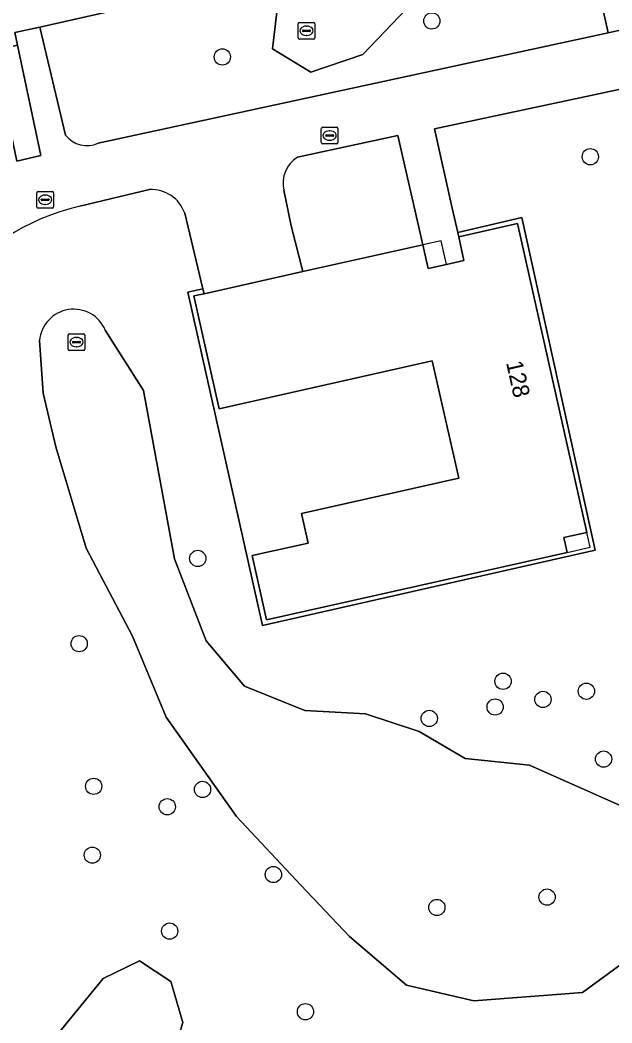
# Model space of a CAD drawing. Extents: x 156661 to 157576, y 383570 to 384425.
# Drawn here: x 156758.2 to 156793.8, y 383881.2 to 383941.5 of the extents above; entities that cross this region are included whole.
import ezdxf

# ---------------------------------------------------------------- set-up
doc = ezdxf.new("R2010")
doc.units = 0
for name, color, linetype in [('IMGEO_Boom', 7, 'Continuous'), ('IMGEO_Erf', 7, 'Continuous'), ('IMGEO_Groenvoorziening', 7, 'Continuous'), ('IMGEO_Meer_plas_ven_vijver', 7, 'Continuous'), ('IMGEO_Pand', 7, 'Continuous'), ('IMGEO_Pand_nummerreeks', 7, 'Continuous'), ('IMGEO_Pand_overbouw', 7, 'Continuous'), ('IMGEO_Rijbaan_lokaal_gesloten', 7, 'Continuous'), ('IMGEO_Rioolput', 7, 'Continuous'), ('IMGEO_Voetpad_open', 7, 'Continuous')]:
    doc.layers.add(name, color=color, linetype=linetype)

msp = doc.modelspace()

# ---------------------------------------------------------------- linework, layer by layer
at = {"layer": 'IMGEO_Boom'}
for centre in [(156782.999, 383941.466), (156770.4, 383939.3), (156792.529, 383933.304), (156768.925, 383909.156), (156761.792, 383904.036), (156787.283, 383901.774), (156792.293, 383901.175), (156786.807, 383900.229), (156789.68, 383900.681), (156782.842, 383899.539), (156793.327, 383897.097), (156762.662, 383895.46), (156769.21, 383895.271), (156767.091, 383894.232), (156762.584, 383891.322), (156773.472, 383890.158), (156789.932, 383888.802), (156783.301, 383888.177), (156767.234, 383886.756), (156775.401, 383881.913)]:
    msp.add_circle(centre, 0.489, dxfattribs=at)
at = {"layer": 'IMGEO_Erf'}
msp.add_lwpolyline([(156783.017, 383921.041), (156770.213, 383918.148), (156768.69, 383924.935), (156769.3, 383925.071), (156769.229, 383925.367), (156768.321, 383925.155), (156772.807, 383905.13), (156792.818, 383909.646), (156788.41, 383929.644), (156784.555, 383928.753), (156784.613, 383928.493), (156788.143, 383929.281), (156792.312, 383910.722), (156790.931, 383910.412), (156791.131, 383909.52), (156773.05, 383905.464), (156772.187, 383909.327), (156775.564, 383910.081), (156775.168, 383911.852), (156784.613, 383913.976)], close=True, dxfattribs=at)
at = {"layer": 'IMGEO_Groenvoorziening'}
for points in [[(156762.934, 383934.118), (156793.6, 383940.758), (156778.599, 384008.292)], [(156751.719, 383933.758), (156750.78, 383938.387), (156745.551, 383937.219), (156741.236, 383956.679), (156746.086, 383957.762), (156760.64, 383960.974), (156761.956, 383955.261), (156762.554, 383952.572), (156762.026, 383952.455), (156764.312, 383942.195), (156759.416, 383941.099), (156760.97, 383934.592)], [(156783.667, 383944.503), (156778.843, 383939.451), (156775.723, 383938.382), (156773.42, 383939.788), (156774.037, 383945.068)], [(156801.01, 383907.365), (156795.487, 383906.115), (156795.088, 383907.896), (156800.623, 383909.14), (156794.353, 383937.37), (156783.169, 383934.99), (156784.232, 383930.211), (156784.555, 383928.753), (156788.41, 383929.644), (156792.818, 383909.646), (156772.807, 383905.13), (156768.321, 383925.155), (156769.229, 383925.367), (156768.136, 383929.92)], [(156775.245, 383926.4), (156782.461, 383928.012), (156780.961, 383934.576), (156774.922, 383933.277)], [(156766.03, 383931.333), (156761.825, 383930.332)], [(156774.107, 383931.292), (156774.533, 383929.146), (156775.245, 383926.4)], [(156763.361, 383922.88), (156765.651, 383919.251), (156767.525, 383909.129), (156769.434, 383904.195), (156771.726, 383901.474), (156775.366, 383900.016), (156779.003, 383899.812), (156782.244, 383898.751), (156785.006, 383897.128), (156788.874, 383896.741), (156795.235, 383893.904), (156797.126, 383892.013), (156797.298, 383887.371), (156795.493, 383885.566), (156792.055, 383883.073), (156785.522, 383882.557), (156781.482, 383883.503), (156778.043, 383886.426), (156775.121, 383889.52), (156771.252, 383893.646), (156767.023, 383899.625), (156764.997, 383904.478)], [(156764.997, 383904.478), (156762.212, 383909.779), (156760.391, 383915.857), (156759.636, 383919.089), (156759.409, 383922.264)]]:
    msp.add_lwpolyline(points, dxfattribs=at)
for points in [[(156758.081, 383940.019), (156756.644, 383939.698), (156758.042, 383933.044), (156759.476, 383933.381)], [(156767.299, 383883.721), (156768.021, 383881.267), (156767.313, 383878.874), (156764.354, 383873.446), (156760.744, 383872.951), (156759.648, 383875.982), (156758.573, 383877.099), (156759.562, 383879.076), (156760.194, 383880.185), (156763.24, 383883.907), (156765.415, 383884.973)], [(156767.313, 383878.874), (156768.021, 383881.267), (156767.299, 383883.721), (156765.415, 383884.973), (156763.24, 383883.907), (156760.194, 383880.185), (156759.562, 383879.076), (156758.573, 383877.099), (156759.648, 383875.982), (156760.744, 383872.951), (156764.354, 383873.446)]]:
    msp.add_lwpolyline(points, close=True, dxfattribs=at)
for centre, radius, start, end in [((156762.262, 383935.638), 1.662, 219.00126, 293.86167), ((156775.898, 383931.716), 1.841, 122.03016, 193.32576), ((156766.126, 383929.2), 2.135, 19.70299, 92.57851), ((156765.181, 383916.263), 14.464, 103.41782, 179.48447), ((156761.462, 383922.078), 2.061, 22.89543, 174.82343)]:
    msp.add_arc(centre, radius, start, end, dxfattribs=at)
at = {"layer": 'IMGEO_Meer_plas_ven_vijver'}
for points in [[(156774.037, 383945.068), (156773.42, 383939.788), (156775.723, 383938.382), (156778.843, 383939.451), (156783.667, 383944.503)], [(156782.244, 383898.751), (156779.003, 383899.812), (156775.366, 383900.016), (156771.726, 383901.474), (156769.434, 383904.195), (156767.525, 383909.129), (156765.651, 383919.251), (156763.361, 383922.88)], [(156759.409, 383922.264), (156759.636, 383919.089), (156760.391, 383915.857), (156762.212, 383909.779), (156764.997, 383904.478), (156767.023, 383899.625), (156771.252, 383893.646), (156775.121, 383889.52), (156778.043, 383886.426), (156781.482, 383883.503), (156785.522, 383882.557), (156792.055, 383883.073), (156795.493, 383885.566), (156797.298, 383887.371), (156797.126, 383892.013), (156795.235, 383893.904), (156788.874, 383896.741), (156785.006, 383897.128), (156782.244, 383898.751)]]:
    msp.add_lwpolyline(points, dxfattribs=at)
msp.add_arc((156761.462, 383922.078), 2.061, 22.89543, 174.82343, dxfattribs=at)
at = {"layer": 'IMGEO_Pand'}
for points in [[(156762.026, 383952.455), (156762.554, 383952.572), (156761.956, 383955.261), (156756.462, 383954.041), (156757.728, 383948.318), (156748.639, 383946.279), (156746.086, 383957.762), (156741.236, 383956.679), (156745.551, 383937.219), (156750.78, 383938.387), (156756.644, 383939.698), (156758.081, 383940.019), (156757.925, 383940.765), (156759.416, 383941.099), (156764.312, 383942.195)], [(156788.143, 383929.281), (156784.613, 383928.493), (156784.932, 383927.058), (156783.882, 383926.824), (156782.78, 383926.578), (156782.461, 383928.012), (156775.245, 383926.4), (156769.3, 383925.071), (156768.69, 383924.935), (156770.213, 383918.148), (156783.017, 383921.041), (156784.613, 383913.976), (156775.168, 383911.852), (156775.564, 383910.081), (156772.187, 383909.327), (156773.05, 383905.464), (156791.131, 383909.52), (156790.931, 383910.412), (156792.312, 383910.722)]]:
    msp.add_lwpolyline(points, close=True, dxfattribs=at)
at = {"layer": 'IMGEO_Pand_overbouw'}
for points in [[(156783.563, 383928.258), (156782.461, 383928.012), (156782.78, 383926.578), (156783.882, 383926.824)], [(156792.312, 383910.722), (156790.931, 383910.412), (156791.131, 383909.52), (156792.512, 383909.829)]]:
    msp.add_lwpolyline(points, close=True, dxfattribs=at)
at = {"layer": 'IMGEO_Rijbaan_lokaal_gesloten'}
for points in [[(156797.583, 383941.621), (156795.59, 383941.189), (156793.6, 383940.758), (156762.934, 383934.118)], [(156760.97, 383934.592), (156759.416, 383941.099), (156757.925, 383940.765), (156758.081, 383940.019), (156759.476, 383933.381), (156758.042, 383933.044), (156756.644, 383939.698), (156750.78, 383938.387), (156751.719, 383933.758)], [(156774.922, 383933.277), (156780.961, 383934.576), (156782.461, 383928.012), (156782.78, 383926.578), (156783.882, 383926.824), (156784.932, 383927.058), (156784.613, 383928.493), (156784.555, 383928.753), (156784.232, 383930.211), (156783.169, 383934.99), (156794.353, 383937.37), (156797.015, 383937.936)], [(156761.825, 383930.332), (156766.03, 383931.333)], [(156768.136, 383929.92), (156769.229, 383925.367), (156769.3, 383925.071), (156775.245, 383926.4), (156774.533, 383929.146), (156774.107, 383931.292)]]:
    msp.add_lwpolyline(points, dxfattribs=at)
for centre, radius, start, end in [((156762.262, 383935.638), 1.662, 219.00126, 293.86167), ((156775.898, 383931.716), 1.841, 122.03016, 193.32576), ((156766.126, 383929.2), 2.135, 19.70299, 92.57851), ((156765.181, 383916.263), 14.464, 103.41782, 179.48447)]:
    msp.add_arc(centre, radius, start, end, dxfattribs=at)
at = {"layer": 'IMGEO_Rioolput'}
for p, q in [((156774.963, 383940.447), (156774.963, 383941.299)), ((156775.038, 383941.373), (156775.89, 383941.373)), ((156775.451, 383941.153), (156775.476, 383941.153)), ((156775.964, 383941.299), (156775.964, 383940.447)), ((156775.222, 383940.867), (156775.222, 383940.879)), ((156775.66, 383940.83), (156775.262, 383940.83)), ((156775.265, 383940.916), (156775.663, 383940.916)), ((156775.474, 383940.593), (156775.449, 383940.593)), ((156775.706, 383940.879), (156775.706, 383940.867)), ((156775.89, 383940.373), (156775.038, 383940.373)), ((156776.354, 383934.15), (156776.354, 383935.002)), ((156776.429, 383935.076), (156777.281, 383935.076)), ((156777.355, 383935.002), (156777.355, 383934.15)), ((156776.613, 383934.57), (156776.613, 383934.582)), ((156777.051, 383934.533), (156776.653, 383934.533)), ((156776.656, 383934.619), (156777.054, 383934.619)), ((156776.842, 383934.856), (156776.867, 383934.856)), ((156777.097, 383934.582), (156777.097, 383934.57)), ((156777.281, 383934.076), (156776.429, 383934.076)), ((156776.865, 383934.296), (156776.84, 383934.296)), ((156759.247, 383930.291), (156759.247, 383931.143)), ((156759.322, 383931.217), (156760.174, 383931.217)), ((156759.549, 383930.76), (156759.947, 383930.76)), ((156759.735, 383930.997), (156759.76, 383930.997)), ((156760.248, 383931.143), (156760.248, 383930.291)), ((156760.174, 383930.217), (156759.322, 383930.217)), ((156759.506, 383930.711), (156759.506, 383930.723)), ((156759.944, 383930.674), (156759.546, 383930.674)), ((156759.758, 383930.437), (156759.733, 383930.437)), ((156759.99, 383930.723), (156759.99, 383930.711)), ((156761.132, 383921.734), (156761.132, 383922.586)), ((156761.207, 383922.66), (156762.059, 383922.66)), ((156761.62, 383922.44), (156761.645, 383922.44)), ((156762.133, 383922.586), (156762.133, 383921.734)), ((156761.391, 383922.154), (156761.391, 383922.166)), ((156761.829, 383922.117), (156761.431, 383922.117)), ((156761.434, 383922.203), (156761.832, 383922.203)), ((156761.643, 383921.88), (156761.618, 383921.88)), ((156761.875, 383922.166), (156761.875, 383922.154)), ((156762.059, 383921.66), (156761.207, 383921.66))]:
    msp.add_line(p, q, dxfattribs=at)
for points in [[(156774.963, 383940.447), (156774.963, 383941.299)], [(156775.038, 383941.373), (156775.89, 383941.373)], [(156775.964, 383941.299), (156775.964, 383940.447)], [(156775.89, 383940.373), (156775.038, 383940.373)], [(156776.354, 383934.15), (156776.354, 383935.002)], [(156776.429, 383935.076), (156777.281, 383935.076)], [(156777.355, 383935.002), (156777.355, 383934.15)], [(156777.281, 383934.076), (156776.429, 383934.076)], [(156759.247, 383930.291), (156759.247, 383931.143)], [(156759.322, 383931.217), (156760.174, 383931.217)], [(156760.248, 383931.143), (156760.248, 383930.291)], [(156760.174, 383930.217), (156759.322, 383930.217)], [(156761.132, 383921.734), (156761.132, 383922.586)], [(156761.207, 383922.66), (156762.059, 383922.66)], [(156762.133, 383922.586), (156762.133, 383921.734)], [(156762.059, 383921.66), (156761.207, 383921.66)]]:
    msp.add_lwpolyline(points, dxfattribs=at)
for centre, radius, start, end in [((156775.04, 383941.297), 0.0765, 91.55205, 178.44795), ((156775.04, 383941.297), 0.0765, 91.55205, 178.44795), ((156775.888, 383941.297), 0.0765, 1.55205, 88.44795), ((156775.888, 383941.297), 0.0765, 1.55205, 88.44795), ((156775.04, 383940.449), 0.0765, 181.55205, 268.44795), ((156775.04, 383940.449), 0.0765, 181.55205, 268.44795), ((156775.262, 383940.876), 0.0403, 85.87752, 175.75265), ((156775.259, 383940.866), 0.0366, 178.93798, 274.71019), ((156775.663, 383940.873), 0.043, 264.86636, 352.45326), ((156775.667, 383940.878), 0.0386, 1.73085, 96.63898), ((156775.888, 383940.449), 0.0765, 271.55205, 358.44795), ((156775.888, 383940.449), 0.0765, 271.55205, 358.44795), ((156776.431, 383935), 0.0765, 91.55205, 178.44795), ((156776.431, 383935), 0.0765, 91.55205, 178.44795), ((156777.279, 383935), 0.0765, 1.55205, 88.44795), ((156777.279, 383935), 0.0765, 1.55205, 88.44795), ((156776.653, 383934.579), 0.0403, 85.87752, 175.75265), ((156776.65, 383934.569), 0.0366, 178.93798, 274.71019), ((156777.054, 383934.576), 0.043, 264.86636, 352.45326), ((156777.058, 383934.581), 0.0386, 1.73085, 96.63898), ((156776.431, 383934.152), 0.0765, 181.55205, 268.44795), ((156776.431, 383934.152), 0.0765, 181.55205, 268.44795), ((156777.279, 383934.152), 0.0765, 271.55205, 358.44795), ((156777.279, 383934.152), 0.0765, 271.55205, 358.44795), ((156759.324, 383931.141), 0.0765, 91.55205, 178.44795), ((156759.324, 383931.141), 0.0765, 91.55205, 178.44795), ((156759.546, 383930.72), 0.0403, 85.87752, 175.75265), ((156759.951, 383930.722), 0.0386, 1.73085, 96.63898), ((156760.172, 383931.141), 0.0765, 1.55205, 88.44795), ((156760.172, 383931.141), 0.0765, 1.55205, 88.44795), ((156759.324, 383930.293), 0.0765, 181.55205, 268.44795), ((156759.324, 383930.293), 0.0765, 181.55205, 268.44795), ((156759.543, 383930.71), 0.0366, 178.93798, 274.71019), ((156759.947, 383930.717), 0.043, 264.86636, 352.45326), ((156760.172, 383930.293), 0.0765, 271.55205, 358.44795), ((156760.172, 383930.293), 0.0765, 271.55205, 358.44795), ((156761.209, 383922.584), 0.0765, 91.55205, 178.44795), ((156761.209, 383922.584), 0.0765, 91.55205, 178.44795), ((156762.057, 383922.584), 0.0765, 1.55205, 88.44795), ((156762.057, 383922.584), 0.0765, 1.55205, 88.44795), ((156761.209, 383921.736), 0.0765, 181.55205, 268.44795), ((156761.209, 383921.736), 0.0765, 181.55205, 268.44795), ((156761.431, 383922.163), 0.0403, 85.87752, 175.75265), ((156761.428, 383922.153), 0.0366, 178.93798, 274.71019), ((156761.832, 383922.16), 0.043, 264.86636, 352.45326), ((156761.836, 383922.165), 0.0386, 1.73085, 96.63898), ((156762.057, 383921.736), 0.0765, 271.55205, 358.44795), ((156762.057, 383921.736), 0.0765, 271.55205, 358.44795)]:
    msp.add_arc(centre, radius, start, end, dxfattribs=at)
for centre, major_axis, ratio, start_param, end_param in [((156775.45, 383940.873), (-0.387, 0.002), 0.722429, 4.712389, 7.853982), ((156775.475, 383940.873), (-0.39, 0.002), 0.717154, 1.570796, 4.712389), ((156776.841, 383934.576), (-0.387, 0.002), 0.722429, 4.712389, 7.853982), ((156776.866, 383934.576), (-0.39, 0.002), 0.717154, 1.570796, 4.712389), ((156759.734, 383930.717), (-0.387, 0.002), 0.722429, 4.712389, 7.853982), ((156759.759, 383930.717), (-0.39, 0.002), 0.717154, 1.570796, 4.712389), ((156761.619, 383922.16), (-0.387, 0.002), 0.722429, 4.712389, 7.853982), ((156761.644, 383922.16), (-0.39, 0.002), 0.717154, 1.570796, 4.712389)]:
    msp.add_ellipse(centre, major_axis=major_axis, ratio=ratio, start_param=start_param, end_param=end_param, dxfattribs=at)
at = {"layer": 'IMGEO_Voetpad_open'}
msp.add_lwpolyline([(156781.235, 384006.002), (156783.294, 384006.453), (156782.661, 384009.212), (156782.408, 384009.165), (156778.599, 384008.292), (156793.6, 383940.758), (156795.59, 383941.189), (156786.905, 383980.313), (156788.201, 383980.63), (156789.615, 383980.975), (156789.272, 383982.501), (156787.859, 383982.142), (156786.625, 383981.827)], close=True, dxfattribs=at)

# ---------------------------------------------------------------- texts
at = {"layer": 'IMGEO_Pand_nummerreeks'}
msp.add_text('128', height=1, rotation=282.66216, dxfattribs=at).set_placement((156787.457, 383920.927))

doc.saveas('drawing.dxf')
